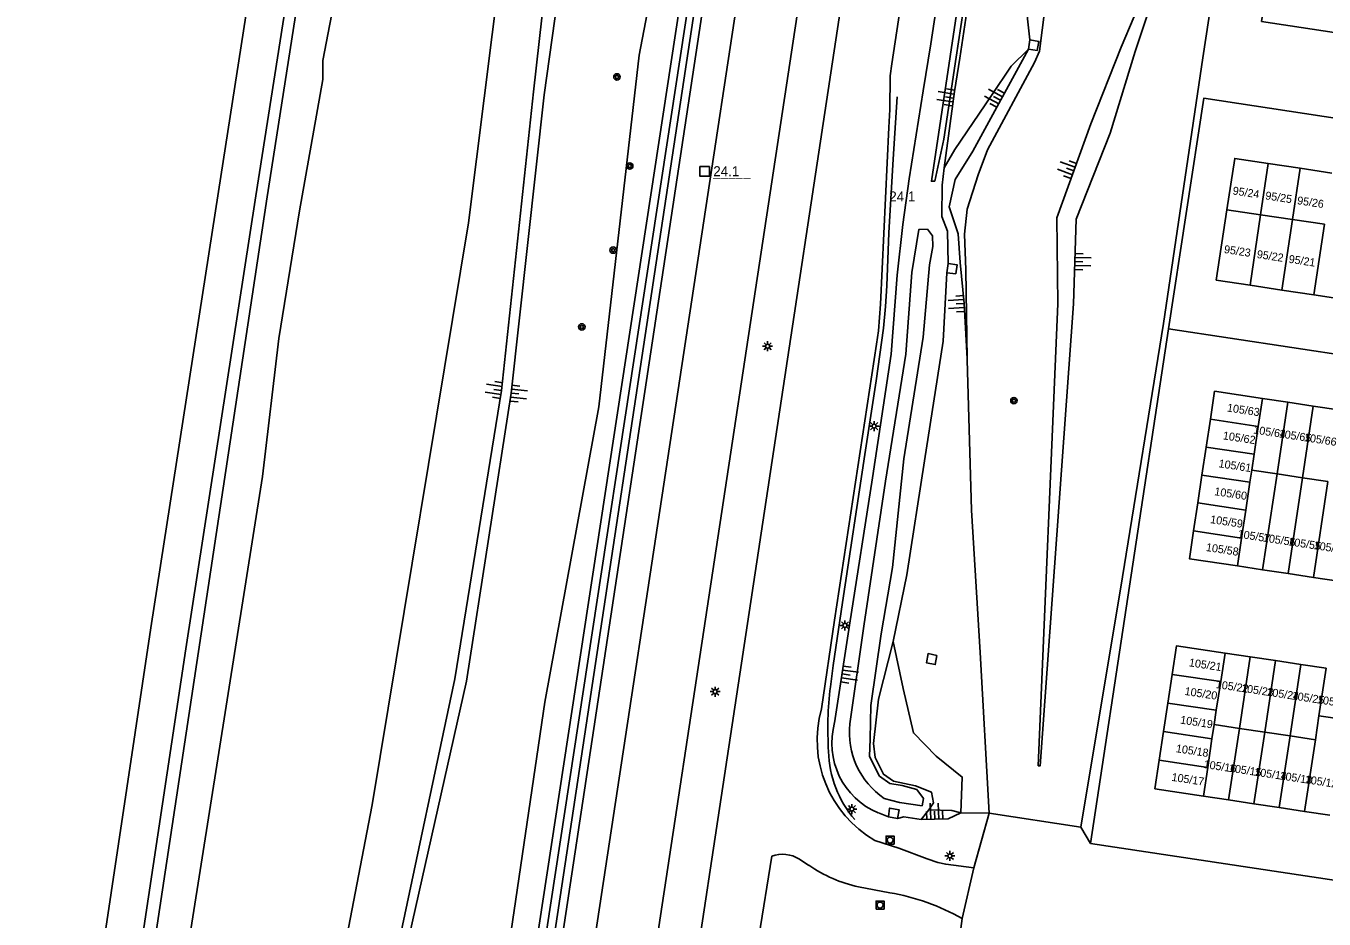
# Model space of a CAD drawing. Extents: x 124000 to 128010, y 398999 to 403000.
# Drawn here: x 126137.5 to 126299.8, y 399094.3 to 399205.9 of the extents above; entities that cross this region are included whole.
import ezdxf

# ---------------------------------------------------------------- set-up
doc = ezdxf.new("R2010")
doc.units = 0
for name, color, linetype in [('gg-afsc-hekwerk', 7, 'Continuous'), ('gg-anno-huisnummerreeks BGT', 7, 'Continuous'), ('gg-bbg-hoofdgebouw', 7, 'Continuous'), ('gg-bbg-tussenscheiding', 7, 'Continuous'), ('gg-knt-BGT kruinlijn', 7, 'Continuous'), ('gg-knt-bovenkant onderkant talud', 7, 'Continuous'), ('gg-knt-verharding', 7, 'Continuous'), ('gg-kntw-bovenkant insteek waterloop', 7, 'Continuous'), ('gg-kntw-waterlijn', 7, 'Continuous'), ('gg-kwrk-uitstroombak niveau min 01', 7, 'Continuous'), ('gt-anno-nummer hm paal', 7, 'Continuous'), ('gt-grn-groengrens', 7, 'Continuous'), ('gt-grn-vlakafsluiter', 7, 'Continuous'), ('gt-knt-geleideconstructie', 7, 'Continuous'), ('gt-symb-boom', 7, 'Continuous'), ('gt-symb-hm paal', 7, 'Continuous'), ('gt-symb-lichtmast', 7, 'Continuous'), ('gt-symb-rioolschacht', 7, 'Continuous'), ('gt-symb-talud symbool', 7, 'Continuous'), ('gx-grn-maaiveld', 7, 'Continuous')]:
    doc.layers.add(name, color=color, linetype=linetype)

# ---------------------------------------------------------------- blocks, each defined once
blk = doc.blocks.new('gt0-TALUD_1')
at = {"layer": 'gt-symb-talud symbool'}
for p, q in [((-1, -1), (-1, 0)), ((-0.5, -2), (-0.5, 0)), ((0, -1), (0, 0)), ((0.5, -2), (0.5, 0)), ((1, -1), (1, 0))]:
    blk.add_line(p, q, dxfattribs=at)
blk = doc.blocks.new('gt0-BOOM')
at = {"layer": 'gt-symb-boom'}
for radius in [0.4, 0.2]:
    blk.add_circle((0, 0), radius, dxfattribs=at)
blk = doc.blocks.new('gt0-RS')
at = {"layer": 'gt-symb-rioolschacht'}
blk.add_lwpolyline([(-0.5, -0.5), (0.5, -0.5), (0.5, 0.5), (-0.5, 0.5)], close=True, dxfattribs=at)
blk.add_circle((0, 0), 0.375, dxfattribs=at)
blk = doc.blocks.new('gt0-LMAST')
at = {"layer": 'gt-symb-lichtmast'}
for p, q in [((-0.18, 0.17), (-0.45, 0.44)), ((-0.01, 0.25), (-0.01, 0.62)), ((0.17, 0.17), (0.44, 0.44)), ((-0.26, 0), (-0.63, 0)), ((-0.18, -0.18), (-0.45, -0.45)), ((-0.01, -0.25), (-0.01, -0.63)), ((0.44, -0.45), (0.17, -0.18)), ((0.24, 0), (0.62, 0))]:
    blk.add_line(p, q, dxfattribs=at)
blk.add_circle((-0.01, 0), 0.25, dxfattribs=at)
blk = doc.blocks.new('gt0-HMpaal')
at = {"layer": 'gt-symb-hm paal'}
blk.add_lwpolyline([(-0.6, 0.6), (0.6, 0.6), (0.6, -0.6), (-0.6, -0.6)], close=True, dxfattribs=at)

msp = doc.modelspace()

# ---------------------------------------------------------------- linework, layer by layer
at = {"layer": 'gg-afsc-hekwerk'}
for p, q in [((126280.32, 399168.04), (126270.59, 399103.74)), ((126356.58, 399156.49), (126280.32, 399168.04)), ((126270.59, 399103.74), (126301.27, 399099.09))]:
    msp.add_line(p, q, dxfattribs=at)
msp.add_lwpolyline([(126399.05, 399179.47), (126284.72, 399196.87), (126280.32, 399168.04)], dxfattribs=at)
at = {"layer": 'gg-bbg-hoofdgebouw'}
for p, q in [((126292.78, 399188.73), (126296.76, 399188.13)), ((126296.76, 399188.13), (126300.75, 399187.53)), ((126286.3, 399174.14), (126287.63, 399182.94)), ((126290.53, 399173.5), (126286.3, 399174.14)), ((126294.5, 399172.9), (126290.53, 399173.5)), ((126298.5, 399172.3), (126294.5, 399172.9)), ((126303.4, 399171.56), (126298.5, 399172.3)), ((126295.25, 399158.87), (126292.08, 399159.34)), ((126298.41, 399158.39), (126295.25, 399158.87)), ((126301.58, 399157.91), (126298.41, 399158.39)), ((126285.56, 399156.76), (126285.04, 399153.27)), ((126285.04, 399153.27), (126284.51, 399149.78)), ((126284.51, 399149.78), (126283.98, 399146.29)), ((126283.98, 399146.29), (126283.46, 399142.81)), ((126288.93, 399138.42), (126292.09, 399137.94)), ((126292.09, 399137.94), (126295.26, 399137.46)), ((126295.26, 399137.46), (126298.43, 399136.98)), ((126298.43, 399136.98), (126301.59, 399136.51)), ((126290.55, 399127.06), (126287.39, 399127.53)), ((126293.71, 399126.58), (126290.55, 399127.06)), ((126296.87, 399126.11), (126293.71, 399126.58)), ((126300.03, 399125.63), (126296.87, 399126.11)), ((126280.79, 399124.86), (126280.25, 399121.28)), ((126280.25, 399121.28), (126279.71, 399117.7)), ((126279.71, 399117.7), (126279.16, 399114.12)), ((126279.16, 399114.12), (126278.62, 399110.54)), ((126278.62, 399110.54), (126284.68, 399109.63)), ((126284.68, 399109.63), (126287.84, 399109.16)), ((126287.84, 399109.16), (126291, 399108.68)), ((126291, 399108.68), (126294.16, 399108.21)), ((126294.16, 399108.21), (126297.32, 399107.73)), ((126297.32, 399107.73), (126300.48, 399107.25))]:
    msp.add_line(p, q, dxfattribs=at)
for points in [[(126358.04, 399196.48), (126291.96, 399206.47), (126296.37, 399235.46), (126377.9, 399223.09), (126377.74, 399221.98)], [(126287.63, 399182.94), (126288.61, 399189.36), (126292.78, 399188.73)], [(126292.08, 399159.34), (126286.09, 399160.25), (126285.56, 399156.76)], [(126283.46, 399142.81), (126282.93, 399139.32), (126288.93, 399138.42)], [(126287.39, 399127.53), (126281.33, 399128.44), (126280.79, 399124.86)]]:
    msp.add_lwpolyline(points, dxfattribs=at)
at = {"layer": 'gg-bbg-tussenscheiding'}
for p, q in [((126292.78, 399188.73), (126291.83, 399182.32)), ((126295.81, 399181.73), (126296.76, 399188.13)), ((126287.63, 399182.94), (126291.83, 399182.32)), ((126291.83, 399182.32), (126290.53, 399173.5)), ((126291.83, 399182.32), (126295.81, 399181.73)), ((126294.5, 399172.9), (126295.81, 399181.73)), ((126295.81, 399181.73), (126299.81, 399181.14)), ((126298.5, 399172.3), (126299.81, 399181.14)), ((126292.08, 399159.34), (126291.55, 399155.86)), ((126293.9, 399149.91), (126295.25, 399158.87)), ((126297.06, 399149.43), (126298.41, 399158.39)), ((126285.56, 399156.76), (126291.55, 399155.86)), ((126291.55, 399155.86), (126291.03, 399152.37)), ((126285.04, 399153.27), (126291.03, 399152.37)), ((126291.03, 399152.37), (126290.73, 399150.39)), ((126290.73, 399150.39), (126290.5, 399148.88)), ((126293.9, 399149.91), (126290.73, 399150.39)), ((126284.51, 399149.78), (126290.5, 399148.88)), ((126290.5, 399148.88), (126289.98, 399145.39)), ((126292.09, 399137.94), (126293.9, 399149.91)), ((126297.06, 399149.43), (126293.9, 399149.91)), ((126295.26, 399137.46), (126297.06, 399149.43)), ((126300.23, 399148.95), (126297.06, 399149.43)), ((126298.43, 399136.98), (126300.23, 399148.95)), ((126283.98, 399146.29), (126289.98, 399145.39)), ((126289.98, 399145.39), (126289.45, 399141.9)), ((126283.46, 399142.81), (126289.45, 399141.9)), ((126289.45, 399141.9), (126288.93, 399138.42)), ((126286.85, 399123.95), (126287.39, 399127.53)), ((126289.19, 399118.1), (126290.55, 399127.06)), ((126292.35, 399117.63), (126293.71, 399126.58)), ((126295.52, 399117.16), (126296.87, 399126.11)), ((126280.79, 399124.86), (126286.85, 399123.95)), ((126299.13, 399119.69), (126300.03, 399125.63)), ((126286.3, 399120.37), (126286.85, 399123.95)), ((126280.25, 399121.28), (126286.3, 399120.37)), ((126286.03, 399118.58), (126286.3, 399120.37)), ((126298.68, 399116.68), (126299.13, 399119.69)), ((126302.29, 399119.22), (126299.13, 399119.69)), ((126285.76, 399116.79), (126286.03, 399118.58)), ((126289.19, 399118.1), (126286.03, 399118.58)), ((126287.84, 399109.16), (126289.19, 399118.1)), ((126292.35, 399117.63), (126289.19, 399118.1)), ((126279.71, 399117.7), (126285.76, 399116.79)), ((126285.22, 399113.21), (126285.76, 399116.79)), ((126291, 399108.68), (126292.35, 399117.63)), ((126295.52, 399117.16), (126292.35, 399117.63)), ((126294.16, 399108.21), (126295.52, 399117.16)), ((126298.68, 399116.68), (126295.52, 399117.16)), ((126297.32, 399107.73), (126298.68, 399116.68)), ((126279.16, 399114.12), (126285.22, 399113.21)), ((126284.68, 399109.63), (126285.22, 399113.21))]:
    msp.add_line(p, q, dxfattribs=at)
at = {"layer": 'gg-knt-BGT kruinlijn'}
for points in [[(126172.52, 399025.36), (126174.65, 399024.86), (126177.33, 399050.19), (126185.03, 399090.46), (126192.58, 399124), (126198.15, 399160.02), (126202.3, 399197.32), (126209.26, 399246.91), (126214.43, 399254.34), (126212.59, 399255.99), (126206.68, 399248.42), (126200.98, 399197.66), (126196.98, 399160.33), (126191.11, 399124.32), (126183.99, 399090.74), (126176.05, 399051.05), (126172.52, 399025.36)], [(126277.67, 399210.96), (126274.4, 399203.24), (126270.62, 399193.67), (126266.37, 399181.91), (126266.48, 399171.17), (126264.03, 399113.42)], [(126264.03, 399113.42), (126264.27, 399113.42), (126268.46, 399171.18), (126268.8, 399181.76), (126273.05, 399192.52), (126276.14, 399202.71), (126278.66, 399210.25)], [(126245.93, 399128.96), (126247.15, 399123.1), (126248.45, 399117.55), (126251.27, 399114.65), (126254.55, 399112.02), (126254.37, 399107.55)], [(126249.42, 399106.72), (126252.79, 399106.81), (126254.37, 399107.55)]]:
    msp.add_lwpolyline(points, dxfattribs=at)
at = {"layer": 'gg-knt-bovenkant onderkant talud'}
msp.add_line((126269.37, 399105.78), (126257.91, 399107.5), dxfattribs=at)
for points in [[(126224.1, 399253.97), (126214.17, 399202.27), (126209.13, 399158.32), (126202.39, 399121.38), (126196.12, 399078.95), (126190.16, 399038.24), (126186.97, 399018.82)], [(126255.16, 399164.31), (126254.99, 399175.42), (126254.84, 399179.9), (126255.15, 399183.02), (126256.52, 399187.29), (126257.72, 399190.43), (126263.56, 399201.35), (126264.2, 399202.78), (126264.88, 399208.01), (126268.44, 399213.31), (126270.89, 399217.05), (126269.86, 399232.37), (126269.26, 399240.08), (126269.35, 399244.46), (126269.96, 399248.69)], [(126262.99, 399204.18), (126262.39, 399209.5), (126264.26, 399219.91), (126266.7, 399233.67), (126267.39, 399241.34), (126267.19, 399242.87), (126266.09, 399246.06), (126266.72, 399248.4), (126269.96, 399248.69)], [(126291.31, 399245.92), (126284.6, 399201.92), (126279.69, 399168.7), (126274.57, 399137.07), (126269.37, 399105.78)], [(126252.3, 399188.16), (126253.62, 399190.47), (126258.22, 399197.23), (126260.67, 399200.88), (126262.81, 399203.02)], [(126253.67, 399186.73), (126255.86, 399190.24), (126262.81, 399203.02)], [(126253.67, 399186.73), (126252.9, 399183.3), (126254.03, 399179.94), (126254.3, 399176.34), (126254.79, 399171.21), (126255.16, 399164.31)], [(126257.91, 399107.5), (126256.78, 399127.59), (126255.7, 399145.37), (126255.16, 399164.17), (126255.16, 399164.31)], [(126250.39, 399107.92), (126253.23, 399107.84), (126254.37, 399107.55)]]:
    msp.add_lwpolyline(points, dxfattribs=at)
at = {"layer": 'gg-knt-verharding'}
for p, q in [((126234.21, 399101.77), (126235.39, 399100.99)), ((126254.52, 399094.34), (126255.98, 399100.67)), ((126241.56, 399098.29), (126245.49, 399097.57))]:
    msp.add_line(p, q, dxfattribs=at)
for points in [[(126250.27, 399365.06), (126250.12, 399365.07), (126198.67, 399026.32)], [(126206.3, 399025.16), (126239.97, 399247.18), (126239.82, 399247.21), (126257.54, 399363.97)], [(126212.41, 399030.2), (126245.12, 399246.34), (126245.27, 399246.33)], [(126236.95, 399120.55), (126238.56, 399131.64), (126243.85, 399166.12), (126244.09, 399167.79), (126244.33, 399171.15), (126245.38, 399193.21), (126245.51, 399195.47), (126245.53, 399199.66), (126245.73, 399201.19), (126249.1, 399223.5), (126252.17, 399243.33), (126252.55, 399245.46)], [(126255.98, 399100.67), (126252.49, 399101.13), (126251.5, 399101.35), (126250.15, 399101.8), (126246.6, 399103.13), (126243.64, 399104.11)], [(126223.57, 399036.37), (126222.46, 399036.64), (126221.06, 399037.04), (126220.93, 399037.7), (126225.94, 399070.86), (126229.12, 399092.07), (126230.73, 399102.15)]]:
    msp.add_lwpolyline(points, dxfattribs=at)
for centre, radius, start, end in [((126250.88, 399116.63), 14.47, 164.3256, 239.9631), ((126232.07, 399098.31), 4.07, 58.2901, 109.1778), ((126245.72, 399116.16), 18.35, 235.7518, 256.8968), ((126240.67, 399069.85), 28.14, 60.5181, 80.1276)]:
    msp.add_arc(centre, radius, start, end, dxfattribs=at)
at = {"layer": 'gg-kntw-bovenkant insteek waterloop'}
for p, q in [((126253.56, 399197.72), (126252.3, 399188.16)), ((126245.31, 399107.04), (126244.06, 399107.54)), ((126249.42, 399106.72), (126250.39, 399107.92))]:
    msp.add_line(p, q, dxfattribs=at)
for points in [[(126138.48, 399000), (126142.43, 399024.5), (126149.93, 399077.67), (126157.52, 399128.04), (126166.25, 399184.69), (126173.94, 399233.57), (126176.11, 399245.61), (126181.11, 399251.99), (126186.66, 399256.46), (126189.42, 399260.51), (126194.04, 399261.74), (126198.08, 399266.9)], [(126165.74, 399027.73), (126171.93, 399062.41), (126180.81, 399108.55), (126192.83, 399181.32), (126201.68, 399251.62), (126204.69, 399256.66), (126208.2, 399260.77), (126213.57, 399262.08), (126220.83, 399260.03)], [(126192.88, 399036), (126226.97, 399258.95), (126228.04, 399260.95)], [(126228.04, 399260.95), (126229.44, 399260.87), (126229.97, 399259.91), (126196.08, 399036.06), (126194.34, 399034.28), (126193.48, 399034.32), (126192.88, 399036)], [(126273.88, 399252.51), (126273.21, 399251.88), (126272.26, 399251.77), (126271.18, 399251.93), (126268.14, 399252.79), (126265.59, 399252.97), (126264.15, 399252.95), (126262.96, 399252.18), (126261.46, 399245.69), (126261.2, 399244.07), (126259.9, 399240.47), (126257.11, 399221.08), (126254.25, 399201.9), (126253.56, 399197.72)], [(126249.66, 399197.81), (126250.6, 399203.69), (126253.42, 399222.14), (126256.51, 399241.3), (126257.46, 399246.34)], [(126247.1, 399181.1), (126247.91, 399186.81), (126249.66, 399197.81)], [(126252.3, 399188.16), (126252.02, 399186), (126251.99, 399182.11), (126252.71, 399180.26), (126252.78, 399176.21)], [(126238.6, 399118.82), (126240.47, 399131), (126243.34, 399149.44), (126245.67, 399164.9), (126246.4, 399174.78), (126247.1, 399181.1)], [(126252.62, 399175.07), (126252.16, 399166.5), (126249.84, 399151.54), (126247.61, 399137.31), (126245.93, 399128.96)], [(126245.93, 399128.96), (126244.08, 399121.75), (126243.46, 399116.22), (126243.68, 399114.49), (126244.72, 399112.37), (126245.96, 399111.53), (126248.71, 399110.92), (126250.69, 399110.15), (126250.95, 399108.82), (126250.39, 399107.92)], [(126249.42, 399106.72), (126247.26, 399107.05), (126246.46, 399106.83)]]:
    msp.add_lwpolyline(points, dxfattribs=at)
msp.add_arc((126247.68, 399116.26), 9.44, 164.227, 247.4389, dxfattribs=at)
at = {"layer": 'gg-kntw-waterlijn'}
for points in [[(126139.92, 399000), (126143.95, 399024.26), (126151.51, 399077.52), (126167.69, 399184.54), (126175.3, 399233.4), (126177.05, 399245.19), (126181.82, 399251.28), (126187.4, 399255.78), (126190.04, 399259.64), (126190.78, 399260.23), (126192.27, 399260.07), (126193.8, 399259.08), (126194.22, 399258.3), (126193.75, 399254.24)], [(126193.91, 399036.1), (126194.12, 399035.49), (126195.14, 399036.53), (126228.93, 399259.72), (126228.83, 399259.91), (126228.62, 399259.92), (126227.94, 399258.63), (126193.91, 399036.1)], [(126143.95, 399000), (126147.47, 399022.71), (126152.23, 399051.87), (126155, 399073.23), (126167.11, 399149.58), (126169.12, 399166.84), (126171.72, 399182.81), (126174.62, 399199.22), (126174.62, 399201.58), (126177.04, 399214.18), (126177.03, 399216.47), (126178.1, 399222.09), (126179.95, 399223.88), (126180.56, 399229.46), (126179.77, 399231.13), (126182.03, 399244.74), (126191.65, 399251.24)], [(126251.12, 399186.52), (126250.69, 399186.51), (126253.02, 399202.08), (126255.91, 399221.36)], [(126256.69, 399221.22), (126253.79, 399202.01), (126252.23, 399191.74), (126251.12, 399186.52)], [(126240.51, 399118.67), (126242.26, 399130.9), (126244.94, 399149.02), (126247.48, 399164.88), (126248.23, 399175.1), (126249.12, 399180.45), (126250.19, 399180.53), (126250.83, 399179.68), (126250.88, 399178.35), (126250.44, 399176.05), (126249.65, 399167.02), (126247.24, 399151.81), (126245.83, 399138.24), (126244.43, 399129.93), (126243.11, 399120.98), (126243.02, 399116.82), (126242.94, 399114.6), (126244.2, 399112.14), (126245.49, 399111.21), (126247.03, 399110.96), (126248.85, 399110.48), (126249.71, 399109.36), (126249.53, 399108.43), (126246.72, 399108.84), (126244.8, 399109.36)]]:
    msp.add_lwpolyline(points, dxfattribs=at)
msp.add_arc((126250.34, 399117.56), 9.9, 173.5184, 235.9242, dxfattribs=at)
at = {"layer": 'gg-kwrk-uitstroombak niveau min 01'}
for p, q in [((126262.81, 399203.02), (126262.99, 399204.18)), ((126252.62, 399175.07), (126252.78, 399176.21)), ((126245.31, 399107.04), (126246.46, 399106.83))]:
    msp.add_line(p, q, dxfattribs=at)
for points in [[(126262.99, 399204.18), (126264.13, 399203.98), (126263.93, 399202.85), (126262.81, 399203.02)], [(126252.78, 399176.21), (126253.91, 399176.07), (126253.74, 399174.93), (126252.62, 399175.07)], [(126251.39, 399127.23), (126250.27, 399127.45), (126250.06, 399126.32), (126251.18, 399126.09), (126251.39, 399127.23)], [(126246.46, 399106.83), (126246.65, 399107.94), (126245.47, 399108.15), (126245.31, 399107.04)]]:
    msp.add_lwpolyline(points, dxfattribs=at)
at = {"layer": 'gt-grn-groengrens'}
msp.add_line((126254.37, 399107.55), (126257.91, 399107.5), dxfattribs=at)
at = {"layer": 'gt-grn-vlakafsluiter'}
for p, q in [((126255.98, 399100.67), (126257.91, 399107.5)), ((126269.37, 399105.78), (126270.59, 399103.74)), ((126254.52, 399094.34), (126253.72, 399088.16))]:
    msp.add_line(p, q, dxfattribs=at)
at = {"layer": 'gt-knt-geleideconstructie'}
msp.add_lwpolyline([(126246.4, 399197.04), (126245.9, 399189.26), (126245.38, 399180.04), (126245.11, 399173.43), (126244.95, 399170.83), (126244.69, 399168.15), (126243.77, 399161.54), (126242.37, 399152.34), (126239.58, 399133.85), (126238.4, 399125.95), (126238.06, 399123.31)], dxfattribs=at)
for centre, radius, start, end in [((126282.82, 399118.02), 45.07, 173.26, 183.5503), ((126251.53, 399115.62), 13.71, 181.618, 220.5695)]:
    msp.add_arc(centre, radius, start, end, dxfattribs=at)
at = {"layer": 'gx-grn-maaiveld'}
msp.add_line((126137.53, 399026.9), (126153.15, 399130.68), dxfattribs=at)
msp.add_lwpolyline([(126175.03, 399271.76), (126161.58, 399185.21), (126153.15, 399130.68)], dxfattribs=at)

# ---------------------------------------------------------------- block references
at = {"layer": 'gt-symb-boom'}
for p in [(126211.39, 399199.54), (126212.99, 399188.4), (126210.92, 399177.89), (126207, 399168.29), (126261, 399159.08)]:
    msp.add_blockref('gt0-BOOM', p, dxfattribs=at)
at = {"layer": 'gt-symb-hm paal'}
msp.add_blockref('gt0-HMpaal', (126222.35, 399187.73), dxfattribs=at)
at = {"layer": 'gt-symb-lichtmast'}
for p in [(126230.23, 399165.88), (126243.54, 399155.89), (126239.9, 399130.99), (126223.67, 399122.7), (126240.76, 399108.02), (126253.01, 399102.17)]:
    msp.add_blockref('gt0-LMAST', p, dxfattribs=at)
at = {"layer": 'gt-symb-rioolschacht'}
for p in [(126245.53, 399104.14), (126244.27, 399096.03)]:
    msp.add_blockref('gt0-RS', p, dxfattribs=at)
at = {"layer": 'gt-symb-talud symbool'}
for p, xscale, yscale, rotation in [((126253.42, 399196.9), 0.9998844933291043, 0.9998844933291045, -99.2079690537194), ((126259.34, 399196.63), 1.00016248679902, 1.0001624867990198, -118.61503162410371), ((126268.5, 399187.79), 0.999599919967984, 0.999599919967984, -109.88516511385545), ((126268.63, 399176.47), 1.000449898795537, 1.000449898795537, 88.28164199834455), ((126254.79, 399171.21), 1.0004049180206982, 1.0004049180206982, -86.96313105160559), ((126196.98, 399160.33), 1.0004608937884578, 1.0004608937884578, -98.68085058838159), ((126198.15, 399160.02), 1.0000679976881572, 1.000067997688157, 83.68511557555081), ((126239.53, 399124.91), 0.9998499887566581, 0.9998499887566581, 81.95093829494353), ((126251.1, 399106.76), 1.000449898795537, 1.000449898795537, -178.28164199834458)]:
    msp.add_blockref('gt0-TALUD_1', p, dxfattribs=dict(at, xscale=xscale, yscale=yscale, rotation=rotation))

# ---------------------------------------------------------------- texts
at = {"layer": 'gg-anno-huisnummerreeks BGT'}
for s, rotation, p in [('95/24', 351.4, (126288.29, 399184.86)), ('95/25', 351.4, (126292.37, 399184.25)), ('95/26', 351.4, (126296.35, 399183.64)), ('95/23', 351.4, (126287.21, 399177.54)), ('95/22', 351.4, (126291.31, 399176.92)), ('95/21', 351.4, (126295.29, 399176.32)), ('105/63', 351.4, (126287.59, 399157.73)), ('105/62', 351.4, (126287.07, 399154.25)), ('105/64', 351.4, (126290.88, 399154.98)), ('105/65', 351.4, (126294.05, 399154.5)), ('105/66', 351.4, (126297.21, 399154.02)), ('105/61', 351.4, (126286.54, 399150.76)), ('105/60', 351.4, (126286.01, 399147.27)), ('105/59', 351.4, (126285.49, 399143.78)), ('105/57', 351.4, (126288.92, 399141.96)), ('105/56', 351.4, (126292.08, 399141.48)), ('105/58', 351.4, (126284.96, 399140.29)), ('105/55', 351.4, (126295.25, 399141)), ('105/54', 351.4, (126298.42, 399140.53)), ('105/21', 351.4, (126282.83, 399125.88)), ('105/20', 351.4, (126282.29, 399122.3)), ('105/22', 351.5, (126286.19, 399123.16)), ('105/23', 351.5, (126289.35, 399122.69)), ('105/24', 351.4, (126292.51, 399122.22)), ('105/25', 351.5, (126295.67, 399121.74)), ('105/26', 351.4, (126298.83, 399121.26)), ('105/19', 351.4, (126281.74, 399118.72)), ('105/18', 351.4, (126281.2, 399115.14)), ('105/16', 351.5, (126284.67, 399113.17)), ('105/15', 351.4, (126287.83, 399112.7)), ('105/14', 351.5, (126290.99, 399112.22)), ('105/17', 351.4, (126280.66, 399111.56)), ('105/13', 351.5, (126294.15, 399111.74)), ('105/12', 351.4, (126297.31, 399111.27))]:
    msp.add_text(s, height=1, rotation=rotation, dxfattribs=at).set_placement(p)
at = {"layer": 'gt-anno-nummer hm paal'}
for p in [(126223.43, 399187.13), (126245.43, 399183.97)]:
    msp.add_text('24.1', height=1.25, dxfattribs=at).set_placement(p)
at = {"layer": 'gt-symb-hm paal'}
msp.add_text('_____', height=1.25, dxfattribs=at).set_placement((126223.43, 399187.13))

doc.saveas('drawing.dxf')
